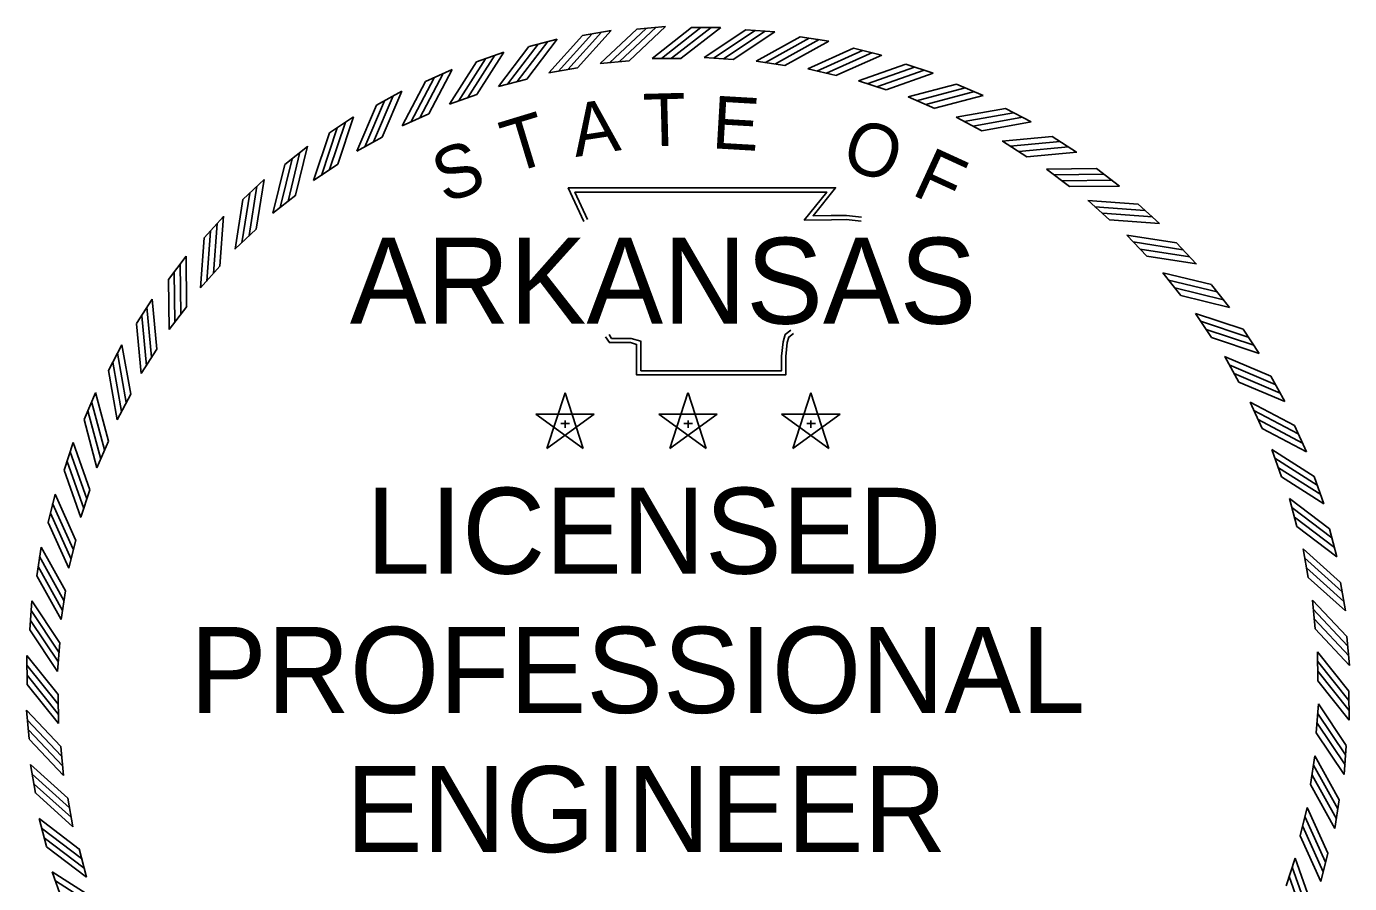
# Model space of a CAD drawing. Extents: x 18 to 14744716, y -5 to 1829144.
# Drawn here: x 42.058 to 44.124, y -3.319 to -1.98 of the extents above; entities that cross this region are included whole.
import ezdxf

# ---------------------------------------------------------------- set-up
doc = ezdxf.new("R2010")
doc.units = 0
doc.layers.add('B_StampERBB', color=7, linetype='Continuous')

msp = doc.modelspace()

# ---------------------------------------------------------------- linework, layer by layer
at = {"layer": 'B_StampERBB'}
for p, q in [((43.011, -1.9842), (43.0561, -1.98)), ((43.0967, -1.9816), (43.1419, -1.9816)), ((42.8428, -2.0113), (42.8865, -1.9998)), ((42.9263, -1.9943), (42.9709, -1.9864)), ((43.1814, -1.985), (43.2266, -1.9883)), ((43.266, -1.996), (43.3107, -2.003)), ((42.7609, -2.0353), (42.8036, -2.0202)), ((43.3494, -2.0139), (43.3933, -2.0246)), ((42.8739, -2.0524), (42.9186, -2.0445)), ((42.954, -2.0378), (42.9991, -2.0336)), ((43.035, -2.0298), (43.0803, -2.0298)), ((43.1163, -2.0285), (43.1616, -2.0318)), ((43.1975, -2.034), (43.2423, -2.041)), ((43.431, -2.0387), (43.4739, -2.053)), ((42.6813, -2.0659), (42.7226, -2.0473)), ((42.7953, -2.0736), (42.8392, -2.0621)), ((43.278, -2.0461), (43.3221, -2.0568)), ((43.3572, -2.0648), (43.4002, -2.0792)), ((42.6045, -2.1029), (42.6441, -2.081)), ((42.7188, -2.1012), (42.7615, -2.0861)), ((43.5103, -2.0701), (43.5519, -2.0879)), ((43.4346, -2.0901), (43.4763, -2.1079)), ((42.5311, -2.1462), (42.5687, -2.1211)), ((42.6448, -2.1351), (42.6861, -2.1165)), ((43.5096, -2.1216), (43.5497, -2.1428)), ((43.5867, -2.1079), (43.6267, -2.1291)), ((42.4614, -2.1954), (42.4968, -2.1673)), ((42.5738, -2.1749), (42.6135, -2.153)), ((43.5818, -2.1592), (43.62, -2.1837)), ((43.6597, -2.152), (43.6978, -2.1763)), ((42.5064, -2.2205), (42.5441, -2.1953)), ((43.6506, -2.2027), (43.6866, -2.2302)), ((43.7289, -2.2019), (43.7648, -2.2293)), ((42.396, -2.2502), (42.429, -2.2192)), ((42.443, -2.2715), (42.4785, -2.2433)), ((43.7156, -2.2516), (43.7492, -2.282)), ((43.7937, -2.2573), (43.8272, -2.2876)), ((42.3354, -2.3102), (42.3658, -2.2766)), ((42.3839, -2.3275), (42.417, -2.2965)), ((43.7763, -2.3058), (43.8073, -2.3389)), ((43.8537, -2.3179), (43.8846, -2.3509)), ((42.28, -2.375), (42.3074, -2.339)), ((42.3298, -2.3882), (42.3602, -2.3546)), ((43.8324, -2.3648), (43.8605, -2.4003)), ((43.9084, -2.3833), (43.9366, -2.4187)), ((42.2301, -2.4441), (42.2545, -2.406)), ((42.2808, -2.4532), (42.3083, -2.4172)), ((43.8833, -2.4283), (43.9085, -2.466)), ((43.9576, -2.4529), (43.9827, -2.4906)), ((42.1861, -2.5171), (42.2072, -2.4772)), ((42.2373, -2.5221), (42.2618, -2.4839)), ((43.9289, -2.4957), (43.9509, -2.5354)), ((44.0009, -2.5264), (44.0228, -2.566)), ((42.1482, -2.5936), (42.166, -2.552)), ((42.1997, -2.5942), (42.2209, -2.5542)), ((42.899, -2.5524), (42.8707, -2.6393)), ((42.9272, -2.6392), (42.8991, -2.5523)), ((43.0909, -2.5524), (43.0626, -2.6393)), ((43.1191, -2.6392), (43.091, -2.5523)), ((43.2828, -2.5524), (43.2545, -2.6393)), ((43.311, -2.6392), (43.2828, -2.5523)), ((43.9688, -2.5666), (43.9874, -2.608)), ((42.9446, -2.5856), (42.8533, -2.5855)), ((42.8534, -2.5856), (42.9272, -2.6393)), ((42.8708, -2.6392), (42.9447, -2.5856)), ((42.8925, -2.6002), (42.9061, -2.6002)), ((42.8991, -2.5953), (42.8991, -2.6067)), ((43.1365, -2.5856), (43.0452, -2.5855)), ((43.0453, -2.5856), (43.1191, -2.6393)), ((43.0627, -2.6392), (43.1366, -2.5856)), ((43.0844, -2.6002), (43.098, -2.6002)), ((43.091, -2.5953), (43.091, -2.6067)), ((43.3284, -2.5856), (43.2371, -2.5855)), ((43.2372, -2.5856), (43.311, -2.6393)), ((43.2546, -2.6392), (43.3285, -2.5856)), ((43.2763, -2.6002), (43.2899, -2.6002)), ((43.2829, -2.5953), (43.2829, -2.6067)), ((44.038, -2.6032), (44.0565, -2.6445)), ((42.1168, -2.6728), (42.1311, -2.6299)), ((42.1682, -2.6693), (42.186, -2.6276)), ((44.0026, -2.6407), (44.0177, -2.6834)), ((44.0686, -2.6828), (44.0837, -2.7255)), ((42.143, -2.7466), (42.1573, -2.7036)), ((42.0921, -2.7545), (42.1028, -2.7105)), ((44.0302, -2.7172), (44.0418, -2.7611)), ((44.0925, -2.7647), (44.104, -2.8084)), ((42.1242, -2.8258), (42.135, -2.7818)), ((42.0741, -2.8378), (42.0812, -2.7931)), ((44.0514, -2.7958), (44.0593, -2.8404)), ((44.1096, -2.8482), (44.1174, -2.8928)), ((42.1121, -2.9063), (42.1191, -2.8615)), ((42.0632, -2.9224), (42.0665, -2.8773)), ((44.0661, -2.8758), (44.0702, -2.921)), ((44.1197, -2.9329), (44.1238, -2.9779)), ((42.1066, -2.9875), (42.11, -2.9423)), ((42.0592, -3.0076), (42.0588, -2.9623)), ((44.0741, -2.9568), (44.0745, -3.0022)), ((42.1079, -3.0689), (42.1075, -3.0235)), ((44.1228, -3.0181), (44.1232, -3.0634)), ((42.0623, -3.0928), (42.0581, -3.0478)), ((44.0753, -3.0382), (44.072, -3.0834)), ((42.1159, -3.1499), (42.1117, -3.1047)), ((44.1188, -3.1033), (44.1155, -3.1484)), ((42.0724, -3.1775), (42.0645, -3.1329)), ((44.0699, -3.1194), (44.0628, -3.1642)), ((42.1305, -3.2299), (42.1227, -3.1853)), ((44.0577, -3.1999), (44.047, -3.2439)), ((44.1078, -3.1879), (44.1008, -3.2326)), ((42.0895, -3.261), (42.078, -3.2173)), ((42.1517, -3.3085), (42.1402, -3.2646)), ((44.039, -3.2791), (44.0247, -3.3221)), ((44.0899, -3.2712), (44.0792, -3.3152)), ((42.1134, -3.3429), (42.0983, -3.3002))]:
    msp.add_line(p, q, dxfattribs=at)
for points in [[(42.9684, -2.0366), (43.0255, -1.983)], [(42.984, -2.0348), (43.0411, -1.9812)], [(42.9991, -2.0336), (43.0561, -1.98)], [(43.0349, -2.0298), (43.0966, -1.9817)], [(43.0495, -2.0299), (43.1112, -1.9818)], [(43.0652, -2.0296), (43.1269, -1.9815)], [(43.0802, -2.0297), (43.142, -1.9816)], [(42.8245, -2.0658), (42.872, -2.0035)], [(42.8391, -2.0621), (42.8866, -1.9998)], [(42.8739, -2.0525), (42.9263, -1.9943)], [(42.8882, -2.0501), (42.9407, -1.9919)], [(42.9036, -2.047), (42.9561, -1.9889)], [(42.9185, -2.0445), (42.9709, -1.9864)], [(42.9539, -2.0378), (43.011, -1.9842)], [(43.1163, -2.0285), (43.1814, -1.9851)], [(43.1308, -2.0297), (43.1959, -1.9863)], [(43.1465, -2.0305), (43.2116, -1.9871)], [(43.1615, -2.0318), (43.2266, -1.9883)], [(43.1975, -2.034), (43.2659, -1.996)], [(43.2118, -2.0364), (43.2803, -1.9984)], [(43.2274, -2.0385), (43.2959, -2.0005)], [(43.2423, -2.041), (43.3107, -2.003)], [(42.7615, -2.0861), (42.8036, -2.0201)], [(42.7953, -2.0737), (42.8427, -2.0114)], [(42.8094, -2.0701), (42.8569, -2.0078)], [(43.2779, -2.0461), (43.3493, -2.014)], [(43.2921, -2.0497), (43.3634, -2.0175)], [(43.3074, -2.0531), (43.3788, -2.0209)], [(42.7188, -2.1013), (42.7609, -2.0353)], [(42.7325, -2.0966), (42.7747, -2.0306)], [(42.7472, -2.091), (42.7894, -2.025)], [(43.322, -2.0568), (43.3934, -2.0246)], [(43.3571, -2.0649), (43.4309, -2.0387)], [(43.3709, -2.0696), (43.4447, -2.0434)], [(42.6581, -2.1293), (42.6946, -2.0601)], [(42.6723, -2.1225), (42.7088, -2.0533)], [(42.6861, -2.1165), (42.7226, -2.0473)], [(43.3859, -2.0742), (43.4597, -2.0481)], [(43.4002, -2.0791), (43.474, -2.053)], [(42.6134, -2.153), (42.6441, -2.081)], [(42.6447, -2.1351), (42.6813, -2.0659)], [(43.4345, -2.0901), (43.5102, -2.0701)], [(43.4478, -2.0959), (43.5235, -2.0759)], [(43.4624, -2.1018), (43.5381, -2.0818)], [(42.5738, -2.175), (42.6045, -2.103)], [(42.5866, -2.1681), (42.6173, -2.0961)], [(42.6002, -2.1601), (42.6309, -2.0881)], [(43.4762, -2.1078), (43.5519, -2.0879)], [(42.5441, -2.1953), (42.5687, -2.1211)], [(43.5095, -2.1216), (43.5866, -2.1079)], [(43.5223, -2.1285), (43.5994, -2.1149)], [(43.5364, -2.1356), (43.6135, -2.1219)], [(42.5064, -2.2206), (42.531, -2.1463)], [(42.5186, -2.2126), (42.5432, -2.1383)], [(42.5314, -2.2036), (42.5561, -2.1293)], [(43.5496, -2.1428), (43.6267, -2.1291)], [(42.4784, -2.2433), (42.4969, -2.1672)], [(43.5817, -2.1592), (43.6596, -2.152)], [(43.5939, -2.1672), (43.6718, -2.1599)], [(43.6073, -2.1754), (43.6853, -2.1681)], [(42.4544, -2.2626), (42.4729, -2.1865)], [(42.4665, -2.2526), (42.485, -2.1765)], [(43.6199, -2.1836), (43.6979, -2.1763)], [(42.4429, -2.2715), (42.4614, -2.1955)], [(43.6505, -2.2027), (43.7288, -2.2019)], [(42.4059, -2.3067), (42.418, -2.2294)], [(42.417, -2.2965), (42.4291, -2.2192)], [(43.662, -2.2116), (43.7403, -2.2108)], [(43.6747, -2.2209), (43.753, -2.2201)], [(43.6866, -2.2301), (43.7649, -2.2293)], [(42.3839, -2.3276), (42.396, -2.2502)], [(42.3946, -2.3177), (42.4067, -2.2404)], [(42.9281, -2.2844), (42.904, -2.2322), (43.3213, -2.2319), (43.2864, -2.2757), (43.3147, -2.2754), (43.3384, -2.2751), (43.3621, -2.2776)], [(42.9341, -2.2816), (42.9144, -2.2388), (43.3076, -2.2386), (43.2726, -2.2825), (43.3148, -2.282), (43.3381, -2.2817), (43.3614, -2.2842)], [(43.7155, -2.2516), (43.7936, -2.2573)], [(43.7262, -2.2615), (43.8043, -2.2672)], [(43.7381, -2.2718), (43.8162, -2.2774)], [(42.3499, -2.3657), (42.3556, -2.2876)], [(42.3601, -2.3546), (42.3658, -2.2765)], [(43.7492, -2.282), (43.8273, -2.2876)], [(42.3298, -2.3883), (42.3354, -2.3102)], [(42.3396, -2.3776), (42.3453, -2.2995)], [(43.7762, -2.3058), (43.8536, -2.3179)], [(43.7861, -2.3165), (43.8634, -2.3286)], [(43.7971, -2.3277), (43.8744, -2.3398)], [(42.299, -2.4291), (42.2982, -2.3508)], [(42.3082, -2.4172), (42.3074, -2.339)], [(43.8073, -2.3388), (43.8847, -2.3509)], [(42.2808, -2.4533), (42.28, -2.375)], [(42.2897, -2.4418), (42.2889, -2.3635)], [(43.8323, -2.3648), (43.9084, -2.3832)], [(43.8412, -2.3763), (43.9173, -2.3947)], [(43.8513, -2.3884), (43.9273, -2.4068)], [(42.2617, -2.4839), (42.2545, -2.406)], [(43.8605, -2.4003), (43.9366, -2.4187)], [(42.2453, -2.5099), (42.2381, -2.432)], [(42.2535, -2.4965), (42.2462, -2.4186)], [(43.8833, -2.4282), (43.9576, -2.4529)], [(42.2373, -2.5221), (42.2301, -2.4442)], [(43.2513, -2.4541), (43.2426, -2.4613), (43.2395, -2.4725), (43.2371, -2.495), (43.2371, -2.5176), (43.0174, -2.5176), (43.0174, -2.4852), (43.0174, -2.4717), (43.0023, -2.4671), (42.9718, -2.4671), (42.9678, -2.4611)], [(43.8912, -2.4404), (43.9655, -2.4651)], [(43.9002, -2.4533), (43.9745, -2.478)], [(42.2209, -2.5542), (42.2072, -2.4771)], [(43.2555, -2.4593), (43.2484, -2.4651), (43.246, -2.4737), (43.2437, -2.4953), (43.2437, -2.5242), (43.0108, -2.5242), (43.0108, -2.4852), (43.0108, -2.4766), (43.0013, -2.4737), (42.9682, -2.4737), (42.9623, -2.4647)], [(43.9085, -2.4659), (43.9828, -2.4906)], [(42.2137, -2.5674), (42.2, -2.4904)], [(43.9288, -2.4957), (44.0008, -2.5264)], [(42.1997, -2.5943), (42.1861, -2.5172)], [(42.2067, -2.5815), (42.193, -2.5044)], [(43.9358, -2.5085), (44.0078, -2.5392)], [(43.9437, -2.522), (44.0157, -2.5528)], [(43.9509, -2.5353), (44.0229, -2.566)], [(42.186, -2.6276), (42.166, -2.5519)], [(42.1741, -2.656), (42.1541, -2.5803)], [(42.1799, -2.6414), (42.1599, -2.5657)], [(43.9687, -2.5666), (44.0379, -2.6032)], [(43.9745, -2.5799), (44.0438, -2.6165)], [(42.1682, -2.6693), (42.1482, -2.5936)], [(43.9813, -2.5941), (44.0505, -2.6307)], [(43.9874, -2.6079), (44.0566, -2.6445)], [(42.1524, -2.7179), (42.1262, -2.6441)], [(42.1573, -2.7037), (42.1311, -2.6299)], [(44.0025, -2.6406), (44.0685, -2.6828)], [(42.1477, -2.7329), (42.1216, -2.6592)], [(44.0073, -2.6544), (44.0732, -2.6965)], [(42.143, -2.7467), (42.1168, -2.6729)], [(44.0128, -2.6691), (44.0788, -2.7112)], [(44.0177, -2.6833), (44.0837, -2.7255)], [(42.1312, -2.7964), (42.099, -2.7251)], [(42.1349, -2.7818), (42.1027, -2.7105)], [(44.0302, -2.7172), (44.0924, -2.7646)], [(42.1278, -2.8118), (42.0957, -2.7404)], [(44.0337, -2.7313), (44.096, -2.7787)], [(44.0381, -2.7464), (44.1003, -2.7938)], [(42.1243, -2.8259), (42.0921, -2.7545)], [(44.0418, -2.761), (44.104, -2.8084)], [(42.1166, -2.8764), (42.0787, -2.808)], [(42.1191, -2.8616), (42.0811, -2.7931)], [(44.0514, -2.7957), (44.1095, -2.8482)], [(42.1145, -2.892), (42.0766, -2.8235)], [(44.0538, -2.8101), (44.1119, -2.8625)], [(44.0568, -2.8255), (44.115, -2.8779)], [(42.1121, -2.9064), (42.0742, -2.8379)], [(44.0593, -2.8404), (44.1175, -2.8928)], [(42.1099, -2.9423), (42.0664, -2.8772)], [(44.066, -2.8758), (44.1196, -2.9328)], [(44.0672, -2.8903), (44.1208, -2.9473)], [(42.1079, -2.973), (42.0644, -2.908)], [(42.1087, -2.9573), (42.0652, -2.8923)], [(44.069, -2.9059), (44.1226, -2.963)], [(42.1067, -2.9876), (42.0632, -2.9225)], [(44.0703, -2.9209), (44.1239, -2.978)], [(42.1075, -3.0236), (42.0587, -2.9623)], [(44.074, -2.9568), (44.1227, -3.018)], [(44.074, -2.9713), (44.1227, -3.0326)], [(42.1075, -3.0387), (42.0587, -2.9774)], [(42.1079, -3.0544), (42.0592, -2.9931)], [(44.0745, -2.987), (44.1232, -3.0483)], [(42.1079, -3.0689), (42.0592, -3.0076)], [(44.0745, -3.0021), (44.1232, -3.0634)], [(42.1117, -3.1048), (42.0581, -3.0477)], [(44.0741, -3.0526), (44.1176, -3.1177)], [(44.0753, -3.0381), (44.1188, -3.1032)], [(42.1129, -3.1198), (42.0593, -3.0627)], [(44.0733, -3.0683), (44.1168, -3.1334)], [(42.1147, -3.1354), (42.0611, -3.0784)], [(42.1159, -3.1499), (42.0623, -3.0929)], [(44.072, -3.0834), (44.1155, -3.1485)], [(42.1226, -3.1853), (42.0645, -3.1329)], [(44.0674, -3.1337), (44.1054, -3.2022)], [(44.0698, -3.1193), (44.1078, -3.1878)], [(42.1251, -3.2002), (42.067, -3.1478)], [(44.0653, -3.1493), (44.1033, -3.2177)], [(42.1282, -3.2156), (42.0701, -3.1632)], [(42.1306, -3.23), (42.0725, -3.1775)], [(44.0629, -3.1641), (44.1008, -3.2326)], [(44.0577, -3.1998), (44.0899, -3.2712)], [(42.1402, -3.2647), (42.0779, -3.2172)], [(44.0541, -3.2139), (44.0863, -3.2853)], [(42.1439, -3.2793), (42.0816, -3.2319)], [(44.0507, -3.2293), (44.0829, -3.3006)], [(42.1482, -3.2944), (42.086, -3.247)], [(42.1518, -3.3085), (42.0895, -3.2611)], [(44.047, -3.2439), (44.0792, -3.3152)], [(44.039, -3.279), (44.0651, -3.3528)], [(42.1642, -3.3424), (42.0983, -3.3002)], [(44.0342, -3.2928), (44.0604, -3.3665)], [(42.1691, -3.3566), (42.1032, -3.3145)], [(44.0296, -3.3078), (44.0558, -3.3816)]]:
    msp.add_lwpolyline(points, dxfattribs=at)

# ---------------------------------------------------------------- texts
for s, rotation, p in [('T', 1.4789, (43.0217, -2.1676)), ('A', 8.6788, (42.9154, -2.184)), ('E', 356.672, (43.127, -2.1701)), ('T', 16.9015, (42.8155, -2.2101)), ('O', 341.2218, (43.3269, -2.1983)), ('S', 19.7726, (42.7108, -2.257)), ('F', 335.3628, (43.4378, -2.2417))]:
    msp.add_text(s, height=0.0823, rotation=rotation, dxfattribs=at).set_placement(p)
for s, height, p in [('ARKANSAS', 0.13433, (42.563, -2.4443)), ('LICENSED', 0.13433, (42.5885, -2.8347)), ('PROFESSIONAL', 0.134326, (42.3135, -3.0522)), ('ENGINEER', 0.13433, (42.5566, -3.2696))]:
    msp.add_text(s, height=height, dxfattribs=at).set_placement(p)

doc.saveas('drawing.dxf')
